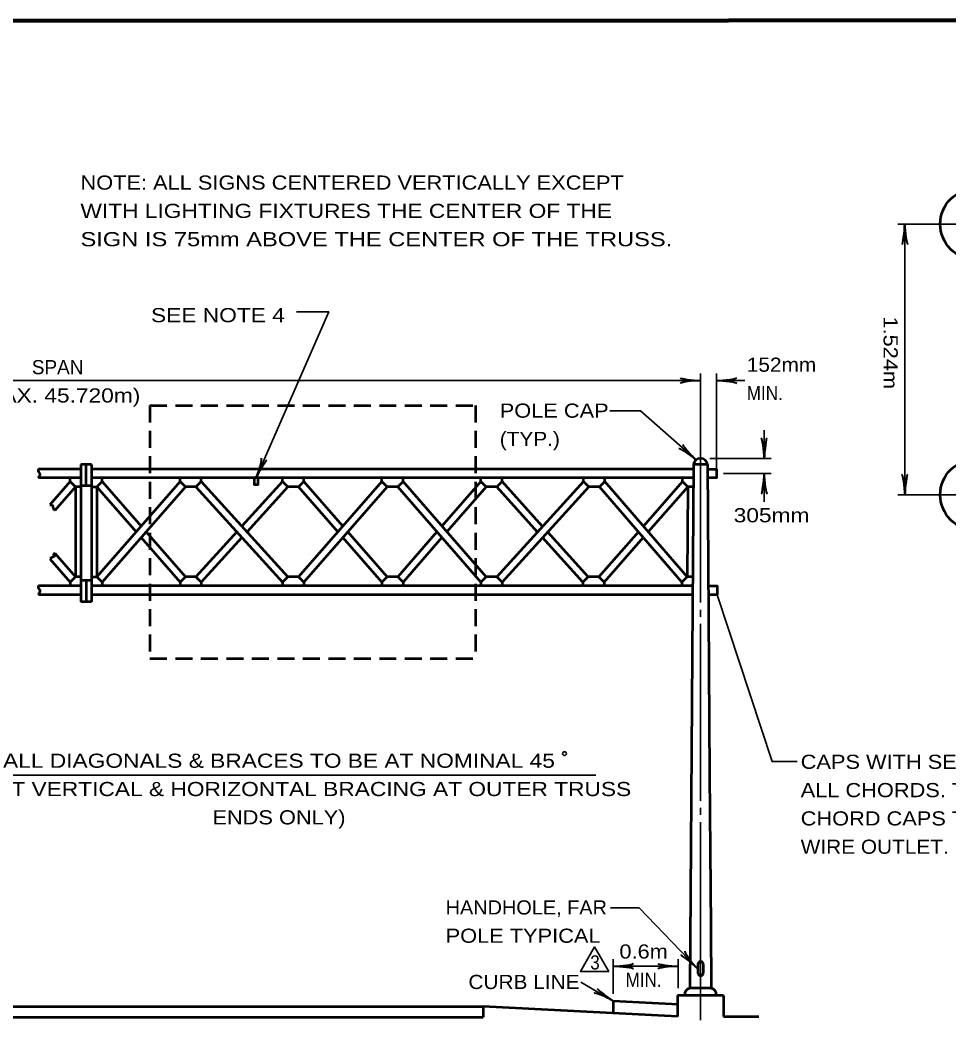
# Model space of a CAD drawing. Extents: x -35 to 821, y -13 to 531.
# Drawn here: x 298.4 to 455.8, y 354.1 to 525.1 of the extents above; entities that cross this region are included whole.
import ezdxf
from ezdxf.enums import TextEntityAlignment as Align

# ---------------------------------------------------------------- set-up
doc = ezdxf.new("R2010")
doc.units = 0
doc.header["$LTSCALE"] = 0.96
doc.linetypes.add('MEDIUM_DASHED', pattern=[4.5, 3, -1.5])
doc.layers.add('1', color=7, linetype='Continuous', lineweight=53)

msp = doc.modelspace()

# ---------------------------------------------------------------- linework, layer by layer
at = {"layer": '1', "lineweight": 35}
for p, q in [((447.1808, 490.5163), (458.2808, 490.5163)), ((448.3808, 490.5163), (448.3808, 444.6163)), ((184.0361, 463.9682), (413.7457, 463.9682)), ((416.4341, 448.9681), (416.4341, 465.1682)), ((416.4341, 463.9682), (421.2341, 463.9682)), ((424.5457, 450.7682), (424.5457, 455.5682)), ((415.3491, 450.7682), (425.7457, 450.7682)), ((417.6341, 448.2181), (425.7457, 448.2181)), ((424.5457, 448.2181), (424.5457, 443.4181)), ((447.1808, 444.6163), (458.2808, 444.6163)), ((413.7457, 423.9181), (413.7457, 425.1181)), ((413.7457, 392.7181), (413.7457, 422.7181)), ((288.6341, 397.0681), (396.0341, 397.0681)), ((413.7457, 390.3181), (413.7457, 391.5181)), ((413.7457, 355.5181), (413.7457, 389.1181)), ((398.9663, 359.9659), (398.9663, 365.8621)), ((398.9663, 364.6621), (409.9542, 364.6621)), ((409.9542, 360.9181), (409.9542, 365.8621)), ((398.9663, 358.7659), (393.4488, 361.9888))]:
    msp.add_line(p, q, dxfattribs=at)
at = {"layer": '1', "linetype": 'MEDIUM_DASHED'}
for p, q in [((320.4341, 459.7681), (320.4341, 416.8681)), ((320.4341, 459.7681), (375.6341, 459.7681)), ((375.6341, 459.7681), (375.6341, 416.8681)), ((320.4341, 416.8681), (375.6341, 416.8681))]:
    msp.add_line(p, q, dxfattribs=at)
at = {"layer": '1'}
for p, q in [((308.7341, 448.9681), (301.5341, 448.9681)), ((308.7341, 449.7181), (308.7341, 426.4681)), ((310.5341, 449.7181), (308.7341, 449.7181)), ((309.6341, 446.1181), (309.6341, 449.7181)), ((310.5341, 449.7181), (310.5341, 426.4681)), ((412.5341, 448.9681), (310.5341, 448.9681)), ((412.5457, 449.7181), (411.9457, 360.9181)), ((414.9457, 449.7181), (412.5457, 449.7181)), ((308.7341, 447.4681), (301.5341, 447.4681)), ((306.9341, 446.8681), (303.4853, 442.9057)), ((306.9341, 446.8681), (306.9341, 447.4681)), ((307.8341, 445.9681), (306.9341, 446.8681)), ((312.3341, 447.4681), (310.5341, 447.4681)), ((311.4341, 445.9681), (312.3341, 446.8681)), ((325.5341, 446.8681), (311.4341, 430.6681)), ((312.3341, 446.8681), (312.3341, 447.4681)), ((312.3341, 446.8681), (318.9341, 439.2851)), ((325.5341, 446.8681), (325.5341, 447.4681)), ((326.4341, 445.9681), (325.5341, 446.8681)), ((328.2341, 445.9681), (329.1341, 446.8681)), ((329.1341, 446.8681), (329.1341, 447.4681)), ((329.1341, 446.8681), (343.8265, 430.6681)), ((342.9265, 446.8681), (336.0303, 439.2643)), ((342.9265, 446.8681), (342.9265, 447.4681)), ((343.8265, 445.9681), (342.9265, 446.8681)), ((345.6265, 445.9681), (346.5265, 446.8681)), ((359.7265, 446.8681), (345.6265, 430.6681)), ((346.5265, 446.8681), (346.5265, 447.4681)), ((353.1265, 439.2851), (346.5265, 446.8681)), ((359.7265, 446.8681), (359.7265, 447.4681)), ((363.3265, 447.4681), (359.7265, 447.4681)), ((360.6265, 445.9681), (359.7265, 446.8681)), ((362.4265, 445.9681), (363.3265, 446.8681)), ((363.3265, 446.8681), (363.3265, 447.4681)), ((377.4265, 430.6681), (363.3265, 446.8681)), ((376.5265, 446.8681), (369.9265, 439.2851)), ((376.5265, 446.8681), (376.5265, 447.4681)), ((377.4265, 445.9681), (376.5265, 446.8681)), ((379.2265, 445.9681), (380.1265, 446.8681)), ((393.9189, 446.8681), (379.2265, 430.6681)), ((380.1265, 446.8681), (380.1265, 447.4681)), ((386.9935, 439.2321), (380.1265, 446.8681)), ((393.9189, 446.8681), (393.9189, 447.4681)), ((394.8189, 445.9681), (393.9189, 446.8681)), ((396.6189, 445.9681), (397.5189, 446.8681)), ((397.5189, 446.8681), (397.5189, 447.4681)), ((411.4952, 430.6681), (397.5189, 446.8681)), ((410.7189, 446.8681), (404.061, 439.2851)), ((410.7189, 446.8681), (410.7189, 447.4681)), ((411.6189, 445.9681), (410.7189, 446.8681)), ((307.8341, 445.9681), (304.3269, 441.9387)), ((307.8341, 445.9681), (307.8341, 430.6681)), ((308.7341, 445.9681), (307.8341, 445.9681)), ((310.5341, 446.1181), (308.7341, 446.1181)), ((310.5341, 445.9681), (311.4341, 445.9681)), ((311.4341, 445.9681), (311.4341, 430.6681)), ((311.4341, 445.9681), (318.0925, 438.3181)), ((326.4341, 445.9681), (312.3341, 429.7681)), ((328.2341, 445.9681), (342.9265, 429.7681)), ((343.8265, 445.9681), (336.8884, 438.3181)), ((352.2848, 438.3181), (345.6265, 445.9681)), ((360.6265, 445.9681), (346.5265, 429.7681)), ((376.5265, 429.7681), (362.4265, 445.9681)), ((377.4265, 445.9681), (370.7682, 438.3181)), ((386.1353, 438.2858), (379.2265, 445.9681)), ((394.8189, 445.9681), (380.1265, 429.7681)), ((410.5952, 429.7681), (396.6189, 445.9681)), ((411.6189, 445.9681), (404.8987, 438.3142)), ((411.6189, 445.9681), (411.4952, 430.6681)), ((412.5189, 445.9681), (411.6189, 445.9681)), ((319.7757, 438.3181), (326.4341, 430.6681)), ((335.1722, 438.3181), (328.2341, 430.6681)), ((360.6265, 430.6681), (353.9681, 438.3181)), ((369.0848, 438.3181), (362.4265, 430.6681)), ((394.6952, 430.6681), (387.848, 438.2819)), ((403.2154, 438.322), (396.4952, 430.6681)), ((318.9341, 437.3511), (325.5341, 429.7681)), ((336.0303, 437.3719), (329.1341, 429.7681)), ((359.7265, 429.7681), (353.1265, 437.3511)), ((369.9265, 437.3511), (363.3265, 429.7681)), ((393.7952, 429.7681), (386.9897, 437.3356)), ((404.0531, 437.3511), (397.3952, 429.7681)), ((304.3271, 434.6973), (307.8341, 430.6681)), ((303.4855, 433.7303), (306.9341, 429.7681)), ((307.8341, 430.6681), (306.9341, 429.7681)), ((306.9341, 429.7681), (306.9341, 429.1681)), ((308.7341, 430.6681), (307.8341, 430.6681)), ((310.5341, 430.0681), (308.7341, 430.0681)), ((309.6341, 430.0681), (309.6341, 426.4681)), ((310.5341, 430.6681), (311.4341, 430.6681)), ((311.4341, 430.6681), (312.3341, 429.7681)), ((312.3341, 429.7681), (312.3341, 429.1681)), ((326.4341, 430.6681), (325.5341, 429.7681)), ((325.5341, 429.7681), (325.5341, 429.1681)), ((328.2341, 430.6681), (326.4341, 430.6681)), ((328.2341, 430.6681), (329.1341, 429.7681)), ((329.1341, 429.7681), (329.1341, 429.1681)), ((343.8265, 430.6681), (342.9265, 429.7681)), ((342.9265, 429.7681), (342.9265, 429.1681)), ((345.6265, 430.6681), (343.8265, 430.6681)), ((345.6265, 430.6681), (346.5265, 429.7681)), ((346.5265, 429.7681), (346.5265, 429.1681)), ((360.6265, 430.6681), (359.7265, 429.7681)), ((359.7265, 429.7681), (359.7265, 429.1681)), ((362.4265, 430.6681), (360.6265, 430.6681)), ((362.4265, 430.6681), (363.3265, 429.7681)), ((363.3265, 429.7681), (363.3265, 429.1681)), ((377.4265, 430.6681), (376.5265, 429.7681)), ((376.5265, 429.7681), (376.5265, 429.1681)), ((379.2265, 430.6681), (377.4265, 430.6681)), ((379.2265, 430.6681), (380.1265, 429.7681)), ((380.1265, 429.7681), (380.1265, 429.1681)), ((394.6952, 430.6681), (393.7952, 429.7681)), ((393.7952, 429.7681), (393.7952, 429.1681)), ((396.4952, 430.6681), (394.6952, 430.6681)), ((396.4952, 430.6681), (397.3952, 429.7681)), ((397.3952, 429.7681), (397.3952, 429.1681)), ((411.4952, 430.6681), (410.5952, 429.7681)), ((410.5952, 429.7681), (410.5952, 429.1681)), ((412.3952, 430.6681), (411.4952, 430.6681)), ((308.7341, 429.1681), (301.5341, 429.1681)), ((308.7341, 427.6681), (301.5341, 427.6681)), ((412.3851, 427.6681), (310.5341, 427.6681)), ((310.5341, 426.4681), (308.7341, 426.4681)), ((415.3005, 397.2187), (415.4749, 371.4192)), ((413.3236, 365.0175), (413.3236, 363.5175)), ((414.2236, 365.0175), (414.2236, 363.5175)), ((417.6457, 359.7181), (409.8457, 359.7181)), ((409.8457, 359.7181), (409.8457, 356.1181)), ((417.6457, 359.7181), (417.6457, 356.1181)), ((409.8457, 356.1181), (376.8909, 357.8452)), ((376.8909, 357.8452), (376.8909, 356.0452)), ((220.8909, 356.0452), (376.8909, 356.0452)), ((417.6457, 356.1181), (423.6457, 356.1181))]:
    msp.add_line(p, q, dxfattribs=at)
at = {"layer": '1', "lineweight": 158}
msp.add_lwpolyline([(814.3112, 525.0846), (22.6112, 524.9846), (22.7112, -1.0154)], dxfattribs=at)
at = {"layer": '1', "lineweight": 35}
for points in [[(338.4124, 447.4681), (350.7536, 475.608), (345.2941, 475.608)], [(413.7457, 426.3181), (413.7457, 450.7682), (413.7457, 465.1682)], [(413.0021, 450.5129), (403.5587, 458.837), (398.358, 458.837)], [(416.5679, 427.6681), (425.8988, 399.3548), (430.1343, 399.3548)], [(413.1253, 364.3725), (403.3427, 374.566), (398.4685, 374.566)]]:
    msp.add_lwpolyline(points, dxfattribs=at)
at = {"layer": '1'}
for points in [[(414.9392, 448.9681), (416.4341, 448.9681), (416.4341, 447.4681), (414.9493, 447.4681)], [(414.9457, 449.7181), (415.118, 424.2181), (415.3006, 397.2187)], [(359.7265, 447.4681), (342.9265, 447.4681), (312.3341, 447.4681)], [(338.7265, 447.4681), (338.7265, 446.2681), (338.1265, 446.2681), (338.1265, 447.4681)], [(412.5189, 447.4681), (410.7189, 447.4681), (363.3265, 447.4681)], [(328.2341, 445.9681), (327.3341, 445.9681), (326.4341, 445.9681)], [(345.6265, 445.9681), (344.7265, 445.9681), (343.8265, 445.9681)], [(362.4265, 445.9681), (361.5265, 445.9681), (360.6265, 445.9681)], [(379.2265, 445.9681), (378.3265, 445.9681), (377.4265, 445.9681)], [(396.6189, 445.9681), (395.7189, 445.9681), (394.8189, 445.9681)], [(363.3265, 429.1681), (359.7265, 429.1681), (312.3341, 429.1681), (310.5341, 429.1681)], [(412.3952, 429.1681), (410.5952, 429.1681), (363.3265, 429.1681)], [(415.073, 429.1681), (416.5679, 429.1681), (416.5679, 427.6681), (415.0831, 427.6681)], [(415.4748, 371.4192), (415.5457, 360.9181), (411.9457, 360.9181)], [(187.9361, 356.1181), (220.8909, 357.8452), (376.8909, 357.8452)], [(409.9542, 358.19), (398.9663, 358.7659), (398.9663, 356.6883)]]:
    msp.add_lwpolyline(points, dxfattribs=at)
at = {"layer": '1', "lineweight": 35}
msp.add_lwpolyline([(395.8037, 367.9336), (393.4037, 363.7767), (398.2037, 363.7767)], close=True, dxfattribs=at)
at = {"layer": '1'}
for centre in [(460.3808, 490.5163), (460.3808, 444.6163)]:
    msp.add_circle(centre, 6, dxfattribs=at)
at = {"layer": '1', "lineweight": 35}
msp.add_circle((390.6975, 400.7164), 0.3199, dxfattribs=at)
at = {"layer": '1'}
for centre, radius, start, end in [((413.7457, 449.5575), 1.2107, 7.62224, 172.37776), ((413.7736, 365.0175), 0.45, 0, 180), ((413.7736, 363.5175), 0.45, 180, 0), ((412.125, 359.8461), 1.0869, 99.49518, 186.76502), ((415.3664, 359.8461), 1.0869, 353.23498, 80.50482)]:
    msp.add_arc(centre, radius, start, end, dxfattribs=at)
at = {"layer": '1', "lineweight": 40}
for centre, major_axis, ratio, start_param, end_param in [((448.1269, 489.1717), (0.2108, 2.1077), 0.07063, 3.14071475, 5.41810995), ((448.1269, 489.1717), (0.2108, 2.1077), 0.07063, 3.14071475, 5.41810995), ((448.7124, 489.2069), (-0.1874, 2.1428), 0.122415, 0.89635335, 3.14159265), ((448.7124, 489.2069), (-0.1874, 2.1428), 0.122415, 0.89635335, 3.14159265), ((412.4363, 463.6366), (2.1428, 0.1874), 0.122415, 0.89635335, 3.14159265), ((412.4011, 464.2221), (2.1077, -0.2108), 0.07063, 3.14071475, 5.41810995), ((417.7787, 463.7143), (-2.1077, 0.2108), 0.07063, 3.14071475, 5.41810995), ((417.7435, 464.2998), (-2.1428, -0.1874), 0.122415, 0.89635335, 3.14159265), ((424.2141, 452.0776), (0.1874, -2.1428), 0.122415, 0.89635335, 3.14159265), ((424.7996, 452.1128), (-0.2108, -2.1077), 0.07063, 3.14071475, 5.41810995), ((411.8006, 451.13), (1.7314, -1.2764), 0.122415, 0.89635335, 3.14159265), ((412.1613, 451.5925), (1.4418, -1.5519), 0.07063, 3.14071475, 5.41810995), ((338.6347, 448.8005), (-0.689, -2.0377), 0.122415, 0.89635335, 3.14159265), ((339.185, 448.5975), (-1.0396, -1.8456), 0.07063, 3.14071475, 5.41810995), ((424.2918, 446.8735), (0.2108, 2.1077), 0.07063, 3.14071475, 5.41810995), ((424.8773, 446.9087), (-0.1874, 2.1428), 0.122415, 0.89635335, 3.14159265), ((448.0492, 445.9257), (0.1874, -2.1428), 0.122415, 0.89635335, 3.14159265), ((448.6347, 445.9609), (-0.2108, -2.1077), 0.07063, 3.14071475, 5.41810995), ((412.0111, 365.1668), (1.6115, -1.3748), 0.07063, 0.86507535, 3.14247055), ((412.4578, 365.5468), (1.3485, -1.6758), 0.122415, 3.14159265, 5.38683196), ((400.3109, 364.4082), (-2.1077, 0.2108), 0.07063, 3.14071475, 5.41810995), ((400.3109, 364.4082), (-2.1077, 0.2108), 0.07063, 3.14071475, 5.41810995), ((400.2757, 364.9937), (-2.1428, -0.1874), 0.122415, 0.89635335, 3.14159265), ((400.2757, 364.9937), (-2.1428, -0.1874), 0.122415, 0.89635335, 3.14159265), ((408.6448, 364.3305), (2.1428, 0.1874), 0.122415, 0.89635335, 3.14159265), ((408.6096, 364.916), (2.1077, -0.2108), 0.07063, 3.14071475, 5.41810995), ((397.9333, 359.6633), (1.7137, -1.2451), 0.07063, 3.14071475, 5.41810995), ((397.6684, 359.1401), (1.9448, -0.919), 0.122415, 0.89635335, 3.14159265)]:
    msp.add_ellipse(centre, major_axis=major_axis, ratio=ratio, start_param=start_param, end_param=end_param, dxfattribs=at)
at = {"layer": '1'}
for points in [[(301.5341, 448.9681), (301.4657, 448.6779), (301.6846, 448.3494), (301.7872, 447.9799), (301.6025, 447.6583), (301.5341, 447.4681)], [(303.4853, 442.9057), (303.8771, 442.8638), (304.0268, 442.3649), (304.3269, 441.9387)], [(304.3271, 434.6973), (304.0767, 434.4317), (304.2762, 434.1823), (303.927, 434.0326), (303.4855, 433.7303)], [(301.5368, 429.1796), (301.4684, 428.8894), (301.6873, 428.5609), (301.7899, 428.1914), (301.6052, 427.8698), (301.5368, 427.6796)]]:
    msp.add_spline(points, degree=3, dxfattribs=at)

# ---------------------------------------------------------------- texts
for s, width, p in [('NOTE: ALL SIGNS CENTERED VERTICALLY EXCEPT', 1.15, (308.6604, 496.3467)), ('WITH LIGHTING FIXTURES THE CENTER OF THE', 1.2, (308.6604, 491.5467)), ('SIGN IS 75mm ABOVE THE CENTER OF THE TRUSS.', 1.25, (308.6604, 486.7467)), ('SEE NOTE 4', 1.2, (320.6109, 473.8686)), ('152mm', 1.1, (421.5917, 465.4652)), ('MIN.', 0.9, (421.5917, 460.6652)), ('POLE CAP', 1.15, (379.7203, 457.6772)), ('(TYP.)', 1.1, (379.7203, 452.8772)), ('305mm', 1.2, (419.3704, 439.9384)), ('CAPS WITH SET SCREWS,', 1.15, (430.7292, 398.1305)), ('ALL CHORDS. TOP FRONT', 1.15, (430.7292, 393.3305)), ('CHORD CAPS TAPPED FOR', 1.15, (430.7292, 388.5305)), ('WIRE OUTLET.', 1.1, (430.7292, 383.7305)), ('HANDHOLE, FAR', 1.05, (370.5525, 373.4373)), ('POLE TYPICAL', 1.15, (370.5525, 368.6373)), ('3', 0.9, (395.0631, 364.1103)), ('CURB LINE', 1.1, (374.4105, 360.8011))]:
    msp.add_text(s, height=2.4, dxfattribs=dict(at, width=width)).set_placement(p)
at = {"layer": '1', "width": 1.15}
msp.add_text('1.524m', height=2.4, rotation=270, dxfattribs=at).set_placement((444.7728, 474.8471))
at = {"layer": '1'}
msp.add_text('SPAN', height=2.4, dxfattribs=at).set_placement((304.7846, 465.0527), align=Align.CENTER)
for s, width, p in [('(MAX. 45.720m)', 1.2, (304.7845, 460.2527)), ('ALL DIAGONALS & BRACES TO BE AT NOMINAL 45', 1.2, (342.3034, 398.3135)), ('(EXCEPT VERTICAL & HORIZONTAL BRACING AT OUTER TRUSS', 1.2, (342.3032, 393.5135)), ('ENDS ONLY)', 1.15, (342.3032, 388.7135)), ('0.6m', 1.15, (404.1062, 365.9656)), ('MIN.', 0.9, (404.1061, 361.1656))]:
    msp.add_text(s, height=2.4, dxfattribs=dict(at, width=width)).set_placement(p, align=Align.CENTER)

doc.saveas('drawing.dxf')
